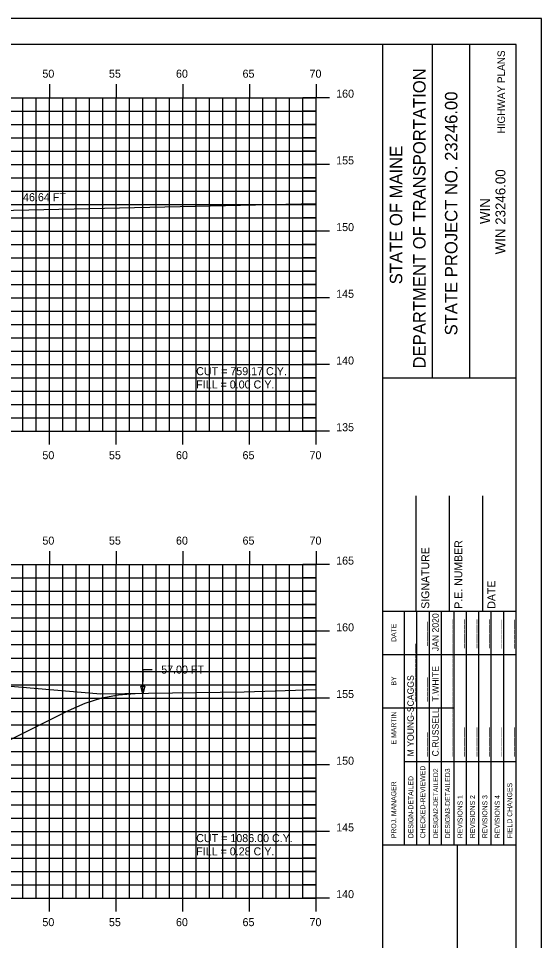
# Model space of a CAD drawing. Extents: x 1143642 to 1143812, y 608981 to 609091.
# Drawn here: x 1143772.5 to 1143811.7, y 609022.2 to 609091.3 of the extents above; entities that cross this region are included whole.
import ezdxf

# ---------------------------------------------------------------- set-up
doc = ezdxf.new("R2010")
doc.units = 0
for name, color, linetype in [('BORDER', 7, 'Continuous'), ('D_Roadway_SlopeLines', 7, 'Continuous'), ('D_Text_Standard', 7, 'Continuous'), ('H_V ANNOTATION', 7, 'Continuous'), ('HIGHWAY_TITLE', 7, 'Continuous'), ('MAJOR', 7, 'Continuous'), ('MINOR', 7, 'Continuous'), ('PLOT BOUNDARY', 7, 'Continuous'), ('S_Roadway_Centerline', 7, 'Continuous')]:
    doc.layers.add(name, color=color, linetype=linetype)

msp = doc.modelspace()

# ---------------------------------------------------------------- linework, layer by layer
msp.add_lwpolyline([(1143686.147, 609035.418), (1143687.397, 609035.592), (1143688.647, 609035.538), (1143689.897, 609035.255), (1143691.147, 609034.744), (1143699.112, 609030.762), (1143702.112, 609031.762), (1143709.835, 609034.336), (1143709.836, 609034.336), (1143713.836, 609034.496), (1143724.836, 609034.716), (1143735.836, 609034.496), (1143748.494, 609033.99), (1143755.665, 609031.599), (1143758.665, 609030.599), (1143776.249, 609039.391), (1143777.499, 609039.941), (1143778.749, 609040.338), (1143779.999, 609040.585), (1143781.249, 609040.679)])
at = {"layer": 'BORDER'}
for p, q in [((1143799.836, 608984.335), (1143799.836, 609089.335)), ((1143803.565, 609064.332), (1143803.565, 609089.332)), ((1143806.36, 609064.332), (1143806.36, 609089.332)), ((1143799.837, 609064.329), (1143809.836, 609064.329)), ((1143802.336, 609046.838), (1143802.336, 609055.485)), ((1143804.836, 609046.838), (1143804.836, 609055.485)), ((1143807.336, 609046.838), (1143807.336, 609055.485)), ((1143799.836, 609046.838), (1143809.836, 609046.838)), ((1143799.836, 609029.338), (1143809.836, 609029.338)), ((1143805.427, 608994.338), (1143805.427, 609029.338))]:
    msp.add_line(p, q, dxfattribs=at)
msp.add_lwpolyline([(1143649.836, 608984.335), (1143809.836, 608984.335), (1143809.836, 609089.335), (1143649.836, 609089.335)], close=True, dxfattribs=at)
for points in [[(1143801.451, 609043.588), (1143801.451, 609046.838)], [(1143802.384, 609029.341), (1143802.384, 609046.838)], [(1143803.315, 609046.838), (1143803.315, 609029.341)], [(1143804.247, 609029.341), (1143804.247, 609046.838)], [(1143805.179, 609029.341), (1143805.179, 609046.838)], [(1143806.111, 609029.341), (1143806.111, 609046.838)], [(1143807.042, 609029.341), (1143807.042, 609046.838)], [(1143807.974, 609029.341), (1143807.974, 609046.838)], [(1143808.906, 609029.341), (1143808.906, 609046.838)], [(1143801.452, 609029.341), (1143801.452, 609046.132)], [(1143799.836, 609043.588), (1143809.836, 609043.588)], [(1143799.836, 609039.588), (1143801.452, 609039.588)], [(1143801.451, 609039.588), (1143805.178, 609039.588)], [(1143801.451, 609035.588), (1143809.836, 609035.588)]]:
    msp.add_lwpolyline(points, dxfattribs=at)
at = {"layer": 'D_Roadway_SlopeLines'}
msp.add_lwpolyline([(1143758.665, 609030.599), (1143776.249, 609039.391), (1143777.499, 609039.941), (1143778.749, 609040.338), (1143779.999, 609040.585), (1143781.249, 609040.679)], dxfattribs=at)
at = {"layer": 'D_Text_Standard'}
msp.add_lwpolyline([(1143781.835, 609040.65), (1143781.851, 609042.467), (1143782.531, 609042.467)], dxfattribs=at)
msp.add_lwpolyline([(1143781.835, 609040.65), (1143781.694, 609041.234), (1143781.985, 609041.231)], close=True, dxfattribs=at)
at = {"layer": 'MAJOR'}
for p, q in [((1143774.836, 609086.337), (1143774.836, 609085.335)), ((1143779.836, 609086.337), (1143779.836, 609085.335)), ((1143784.836, 609086.337), (1143784.836, 609085.335)), ((1143789.836, 609086.337), (1143789.836, 609085.335)), ((1143794.836, 609086.337), (1143794.836, 609085.335)), ((1143654.836, 609085.335), (1143794.836, 609085.335)), ((1143654.836, 609085.335), (1143794.836, 609085.335)), ((1143774.836, 609060.335), (1143774.836, 609085.335)), ((1143779.836, 609060.335), (1143779.836, 609085.335)), ((1143784.836, 609060.335), (1143784.836, 609085.335)), ((1143789.836, 609060.335), (1143789.836, 609085.335)), ((1143795.838, 609085.335), (1143793.834, 609085.335)), ((1143794.836, 609060.335), (1143794.836, 609085.335)), ((1143794.836, 609060.335), (1143794.836, 609085.335)), ((1143654.836, 609080.335), (1143794.836, 609080.335)), ((1143795.838, 609080.335), (1143793.834, 609080.335)), ((1143654.836, 609075.335), (1143794.836, 609075.335)), ((1143795.838, 609075.335), (1143793.834, 609075.335)), ((1143654.836, 609070.335), (1143794.836, 609070.335)), ((1143795.838, 609070.335), (1143793.834, 609070.335)), ((1143654.836, 609065.335), (1143794.836, 609065.335)), ((1143795.838, 609065.335), (1143793.834, 609065.335)), ((1143654.836, 609060.335), (1143794.836, 609060.335)), ((1143654.836, 609060.335), (1143794.836, 609060.335)), ((1143774.836, 609059.333), (1143774.836, 609060.335)), ((1143779.836, 609059.333), (1143779.836, 609060.335)), ((1143784.836, 609059.333), (1143784.836, 609060.335)), ((1143789.836, 609059.333), (1143789.836, 609060.335)), ((1143795.838, 609060.335), (1143793.834, 609060.335)), ((1143794.836, 609059.333), (1143794.836, 609060.335)), ((1143774.836, 609051.337), (1143774.836, 609050.335)), ((1143779.836, 609051.337), (1143779.836, 609050.335)), ((1143784.836, 609051.337), (1143784.836, 609050.335)), ((1143789.836, 609051.337), (1143789.836, 609050.335)), ((1143794.836, 609051.337), (1143794.836, 609050.335)), ((1143654.836, 609050.335), (1143794.836, 609050.335)), ((1143654.836, 609050.335), (1143794.836, 609050.335)), ((1143774.836, 609025.335), (1143774.836, 609050.335)), ((1143779.836, 609025.335), (1143779.836, 609050.335)), ((1143784.836, 609025.335), (1143784.836, 609050.335)), ((1143789.836, 609025.335), (1143789.836, 609050.335)), ((1143795.838, 609050.335), (1143793.834, 609050.335)), ((1143794.836, 609025.335), (1143794.836, 609050.335)), ((1143794.836, 609025.335), (1143794.836, 609050.335)), ((1143654.836, 609045.335), (1143794.836, 609045.335)), ((1143795.838, 609045.335), (1143793.834, 609045.335)), ((1143654.836, 609040.335), (1143794.836, 609040.335)), ((1143795.838, 609040.335), (1143793.834, 609040.335)), ((1143654.836, 609035.335), (1143794.836, 609035.335)), ((1143795.838, 609035.335), (1143793.834, 609035.335)), ((1143654.836, 609030.335), (1143794.836, 609030.335)), ((1143795.838, 609030.335), (1143793.834, 609030.335)), ((1143654.836, 609025.335), (1143794.836, 609025.335)), ((1143654.836, 609025.335), (1143794.836, 609025.335)), ((1143774.836, 609024.333), (1143774.836, 609025.335)), ((1143779.836, 609024.333), (1143779.836, 609025.335)), ((1143784.836, 609024.333), (1143784.836, 609025.335)), ((1143789.836, 609024.333), (1143789.836, 609025.335)), ((1143795.838, 609025.335), (1143793.834, 609025.335)), ((1143794.836, 609024.333), (1143794.836, 609025.335))]:
    msp.add_line(p, q, dxfattribs=at)
at = {"layer": 'MINOR'}
for p, q in [((1143772.836, 609060.335), (1143772.836, 609085.335)), ((1143773.836, 609060.335), (1143773.836, 609085.335)), ((1143775.836, 609060.335), (1143775.836, 609085.335)), ((1143776.836, 609060.335), (1143776.836, 609085.335)), ((1143777.836, 609060.335), (1143777.836, 609085.335)), ((1143778.836, 609060.335), (1143778.836, 609085.335)), ((1143780.836, 609060.335), (1143780.836, 609085.335)), ((1143781.836, 609060.335), (1143781.836, 609085.335)), ((1143782.836, 609060.335), (1143782.836, 609085.335)), ((1143783.836, 609060.335), (1143783.836, 609085.335)), ((1143785.836, 609060.335), (1143785.836, 609085.335)), ((1143786.836, 609060.335), (1143786.836, 609085.335)), ((1143787.836, 609060.335), (1143787.836, 609085.335)), ((1143788.836, 609060.335), (1143788.836, 609085.335)), ((1143790.836, 609060.335), (1143790.836, 609085.335)), ((1143791.836, 609060.335), (1143791.836, 609085.335)), ((1143792.836, 609060.335), (1143792.836, 609085.335)), ((1143793.836, 609060.335), (1143793.836, 609085.335)), ((1143654.836, 609084.335), (1143794.836, 609084.335)), ((1143794.836, 609084.335), (1143793.834, 609084.335)), ((1143654.836, 609083.335), (1143794.836, 609083.335)), ((1143794.836, 609083.335), (1143793.834, 609083.335)), ((1143654.836, 609082.335), (1143794.836, 609082.335)), ((1143794.836, 609082.335), (1143793.834, 609082.335)), ((1143654.836, 609081.335), (1143794.836, 609081.335)), ((1143794.836, 609081.335), (1143793.834, 609081.335)), ((1143654.836, 609079.335), (1143794.836, 609079.335)), ((1143794.836, 609079.335), (1143793.834, 609079.335)), ((1143654.836, 609078.335), (1143794.836, 609078.335)), ((1143794.836, 609078.335), (1143793.834, 609078.335)), ((1143654.836, 609077.335), (1143794.836, 609077.335)), ((1143794.836, 609077.335), (1143793.834, 609077.335)), ((1143654.836, 609076.335), (1143794.836, 609076.335)), ((1143794.836, 609076.335), (1143793.834, 609076.335)), ((1143654.836, 609074.335), (1143794.836, 609074.335)), ((1143794.836, 609074.335), (1143793.834, 609074.335)), ((1143654.836, 609073.335), (1143794.836, 609073.335)), ((1143794.836, 609073.335), (1143793.834, 609073.335)), ((1143654.836, 609072.335), (1143794.836, 609072.335)), ((1143794.836, 609072.335), (1143793.834, 609072.335)), ((1143654.836, 609071.335), (1143794.836, 609071.335)), ((1143794.836, 609071.335), (1143793.834, 609071.335)), ((1143654.836, 609069.335), (1143794.836, 609069.335)), ((1143794.836, 609069.335), (1143793.834, 609069.335)), ((1143654.836, 609068.335), (1143794.836, 609068.335)), ((1143794.836, 609068.335), (1143793.834, 609068.335)), ((1143654.836, 609067.335), (1143794.836, 609067.335)), ((1143794.836, 609067.335), (1143793.834, 609067.335)), ((1143654.836, 609066.335), (1143794.836, 609066.335)), ((1143794.836, 609066.335), (1143793.834, 609066.335)), ((1143654.836, 609064.335), (1143794.836, 609064.335)), ((1143794.836, 609064.335), (1143793.834, 609064.335)), ((1143654.836, 609063.335), (1143794.836, 609063.335)), ((1143794.836, 609063.335), (1143793.834, 609063.335)), ((1143654.836, 609062.335), (1143794.836, 609062.335)), ((1143794.836, 609062.335), (1143793.834, 609062.335)), ((1143654.836, 609061.335), (1143794.836, 609061.335)), ((1143794.836, 609061.335), (1143793.834, 609061.335)), ((1143772.836, 609025.335), (1143772.836, 609050.335)), ((1143773.836, 609025.335), (1143773.836, 609050.335)), ((1143775.836, 609025.335), (1143775.836, 609050.335)), ((1143776.836, 609025.335), (1143776.836, 609050.335)), ((1143777.836, 609025.335), (1143777.836, 609050.335)), ((1143778.836, 609025.335), (1143778.836, 609050.335)), ((1143780.836, 609025.335), (1143780.836, 609050.335)), ((1143781.836, 609025.335), (1143781.836, 609050.335)), ((1143782.836, 609025.335), (1143782.836, 609050.335)), ((1143783.836, 609025.335), (1143783.836, 609050.335)), ((1143785.836, 609025.335), (1143785.836, 609050.335)), ((1143786.836, 609025.335), (1143786.836, 609050.335)), ((1143787.836, 609025.335), (1143787.836, 609050.335)), ((1143788.836, 609025.335), (1143788.836, 609050.335)), ((1143790.836, 609025.335), (1143790.836, 609050.335)), ((1143791.836, 609025.335), (1143791.836, 609050.335)), ((1143792.836, 609025.335), (1143792.836, 609050.335)), ((1143793.836, 609025.335), (1143793.836, 609050.335)), ((1143654.836, 609049.335), (1143794.836, 609049.335)), ((1143794.836, 609049.335), (1143793.834, 609049.335)), ((1143654.836, 609048.335), (1143794.836, 609048.335)), ((1143794.836, 609048.335), (1143793.834, 609048.335)), ((1143654.836, 609047.335), (1143794.836, 609047.335)), ((1143794.836, 609047.335), (1143793.834, 609047.335)), ((1143654.836, 609046.335), (1143794.836, 609046.335)), ((1143794.836, 609046.335), (1143793.834, 609046.335)), ((1143654.836, 609044.335), (1143794.836, 609044.335)), ((1143794.836, 609044.335), (1143793.834, 609044.335)), ((1143654.836, 609043.335), (1143794.836, 609043.335)), ((1143794.836, 609043.335), (1143793.834, 609043.335)), ((1143654.836, 609042.335), (1143794.836, 609042.335)), ((1143794.836, 609042.335), (1143793.834, 609042.335)), ((1143654.836, 609041.335), (1143794.836, 609041.335)), ((1143794.836, 609041.335), (1143793.834, 609041.335)), ((1143654.836, 609039.335), (1143794.836, 609039.335)), ((1143794.836, 609039.335), (1143793.834, 609039.335)), ((1143654.836, 609038.335), (1143794.836, 609038.335)), ((1143794.836, 609038.335), (1143793.834, 609038.335)), ((1143654.836, 609037.335), (1143794.836, 609037.335)), ((1143794.836, 609037.335), (1143793.834, 609037.335)), ((1143654.836, 609036.335), (1143794.836, 609036.335)), ((1143794.836, 609036.335), (1143793.834, 609036.335)), ((1143654.836, 609034.335), (1143794.836, 609034.335)), ((1143794.836, 609034.335), (1143793.834, 609034.335)), ((1143654.836, 609033.335), (1143794.836, 609033.335)), ((1143794.836, 609033.335), (1143793.834, 609033.335)), ((1143654.836, 609032.335), (1143794.836, 609032.335)), ((1143794.836, 609032.335), (1143793.834, 609032.335)), ((1143654.836, 609031.335), (1143794.836, 609031.335)), ((1143794.836, 609031.335), (1143793.834, 609031.335)), ((1143654.836, 609029.335), (1143794.836, 609029.335)), ((1143794.836, 609029.335), (1143793.834, 609029.335)), ((1143654.836, 609028.335), (1143794.836, 609028.335)), ((1143794.836, 609028.335), (1143793.834, 609028.335)), ((1143654.836, 609027.335), (1143794.836, 609027.335)), ((1143794.836, 609027.335), (1143793.834, 609027.335)), ((1143654.836, 609026.335), (1143794.836, 609026.335)), ((1143794.836, 609026.335), (1143793.834, 609026.335))]:
    msp.add_line(p, q, dxfattribs=at)
at = {"layer": 'PLOT BOUNDARY'}
msp.add_lwpolyline([(1143641.743, 608981.276), (1143811.743, 608981.276), (1143811.743, 609091.276), (1143641.743, 609091.276)], close=True, dxfattribs=at)
at = {"layer": 'S_Roadway_Centerline'}
for points in [[(1143654.836, 609073.452), (1143656.779, 609073.558), (1143670.077, 609074.012), (1143673.562, 609073.936), (1143684.029, 609071.706), (1143685.439, 609071.188), (1143689.293, 609072.087), (1143689.817, 609072.189), (1143692.998, 609072.514), (1143693.234, 609072.55), (1143703.514, 609072.846), (1143704.706, 609072.868), (1143705.911, 609072.799), (1143715.089, 609072.281), (1143715.529, 609072.252), (1143719.31, 609071.914), (1143720.106, 609071.688), (1143723.487, 609070.975), (1143725.236, 609072.046), (1143730.481, 609074.786), (1143737.909, 609075.389), (1143759.635, 609076.642), (1143794.836, 609077.413)], [(1143702.154, 609036.699), (1143712.738, 609036.093), (1143713.583, 609036.064), (1143713.855, 609036.051), (1143717.188, 609035.836), (1143717.76, 609035.729), (1143721.488, 609034.942), (1143725.854, 609037.612), (1143731.056, 609040.033), (1143753.174, 609041.724), (1143765.131, 609041.807), (1143778.68, 609040.64), (1143789.442, 609040.804), (1143794.836, 609040.98)]]:
    msp.add_lwpolyline(points, dxfattribs=at)

# ---------------------------------------------------------------- texts
at = {"layer": 'BORDER'}
for s, height, p in [('DEPARTMENT OF TRANSPORTATION', 0.93176, (1143803.043, 609065.041)), ('STATE PROJECT NO. 23246.00', 0.93176, (1143805.428, 609067.517)), ('STATE OF MAINE', 0.93176, (1143801.292, 609071.347)), ('WIN 23246.00', 0.74527, (1143809.032, 609073.596)), ('WIN', 0.7453, (1143807.873, 609075.865)), ('P.E. NUMBER', 0.59055, (1143805.797, 609047.03)), ('SIGNATURE', 0.5906, (1143803.317, 609047.03)), ('DATE', 0.5906, (1143808.277, 609047.03)), ('JAN 2020', 0.4845, (1143804.023, 609043.843)), ('DATE', 0.3714, (1143800.841, 609044.544)), ('_____', 0.4845, (1143803.054, 609044.243)), ('______', 0.4845, (1143804.917, 609044.063)), ('______', 0.4845, (1143805.849, 609044.065)), ('______', 0.4845, (1143806.78, 609044.067)), ('______', 0.4845, (1143807.712, 609044.067)), ('______', 0.4845, (1143808.644, 609044.036)), ('______', 0.4845, (1143809.575, 609044.036)), ('____________', 0.48455, (1143802.159, 609040.073)), ('____________', 0.48455, (1143804.917, 609040.073)), ('T.WHITE', 0.4845, (1143804.023, 609040.073)), ('BY', 0.3714, (1143800.841, 609041.273)), ('M YOUNG-SCAGGS', 0.48455, (1143802.159, 609035.961)), ('_____', 0.4845, (1143803.091, 609040.073)), ('____________', 0.48455, (1143804.917, 609035.961)), ('C.RUSSELL', 0.4845, (1143804.023, 609035.961)), ('E MARTIN', 0.3727, (1143800.841, 609036.855)), ('______', 0.4845, (1143805.849, 609035.961)), ('______', 0.4845, (1143806.78, 609035.961)), ('______', 0.4845, (1143807.712, 609035.961)), ('______', 0.4845, (1143808.644, 609035.961)), ('______', 0.4845, (1143809.575, 609035.961)), ('_____', 0.4845, (1143803.054, 609035.961)), ('CHECKED-REVIEWED', 0.37275, (1143803.017, 609029.826)), ('DESIGN2-DETAILED2', 0.37275, (1143803.986, 609029.826)), ('DESIGN3-DETAILED3', 0.37275, (1143804.881, 609029.826)), ('DESIGN-DETAILED', 0.37275, (1143802.123, 609029.826)), ('PROJ. MANAGER', 0.37275, (1143800.841, 609029.826)), ('FIELD CHANGES', 0.37275, (1143809.539, 609029.826)), ('REVISIONS 1', 0.37275, (1143805.812, 609029.826)), ('REVISIONS 2', 0.37275, (1143806.744, 609029.826)), ('REVISIONS 3', 0.37275, (1143807.676, 609029.826)), ('REVISIONS 4', 0.37275, (1143808.607, 609029.826))]:
    msp.add_text(s, height=height, rotation=90, dxfattribs=at).set_placement(p)
at = {"layer": 'D_Text_Standard'}
for s, p in [('46.64 FT', (1143772.849, 609077.577)), ('CUT = 759.17 C.Y.', (1143785.836, 609064.535)), ('FILL = 0.00 C.Y.', (1143785.836, 609063.539)), ('57.00 FT', (1143783.211, 609042.167)), ('CUT = 1086.00 C.Y.', (1143785.836, 609029.535)), ('FILL = 0.28 C.Y.', (1143785.836, 609028.539))]:
    msp.add_text(s, height=0.6, dxfattribs=at).set_placement(p)
at = {"layer": 'H_V ANNOTATION'}
for s, p in [('50', (1143774.301, 609086.835)), ('55', (1143779.293, 609086.835)), ('60', (1143784.322, 609086.835)), ('65', (1143789.314, 609086.835)), ('70', (1143794.338, 609086.835)), ('160', (1143796.336, 609085.335)), ('155', (1143796.336, 609080.335)), ('150', (1143796.336, 609075.335)), ('145', (1143796.336, 609070.335)), ('140', (1143796.336, 609065.335)), ('135', (1143796.336, 609060.335)), ('50', (1143774.301, 609058.235)), ('60', (1143784.322, 609058.235)), ('65', (1143789.314, 609058.235)), ('70', (1143794.338, 609058.235)), ('55', (1143779.293, 609058.235)), ('50', (1143774.301, 609051.835)), ('55', (1143779.293, 609051.835)), ('60', (1143784.322, 609051.835)), ('65', (1143789.314, 609051.835)), ('70', (1143794.338, 609051.835)), ('165', (1143796.336, 609050.335)), ('160', (1143796.336, 609045.335)), ('155', (1143796.336, 609040.335)), ('150', (1143796.336, 609035.335)), ('145', (1143796.336, 609030.335)), ('140', (1143796.336, 609025.335)), ('50', (1143774.301, 609023.235)), ('55', (1143779.293, 609023.235)), ('60', (1143784.322, 609023.235)), ('65', (1143789.314, 609023.235)), ('70', (1143794.338, 609023.235))]:
    msp.add_text(s, height=0.6, dxfattribs=at).set_placement(p)
at = {"layer": 'HIGHWAY_TITLE'}
msp.add_text('HIGHWAY PLANS', height=0.55901, rotation=90, dxfattribs=at).set_placement((1143808.995, 609082.65))

doc.saveas('drawing.dxf')
